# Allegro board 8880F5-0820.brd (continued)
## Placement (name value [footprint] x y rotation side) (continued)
NOREF#2148  -  []  192.47 182.06 90 top
NOREF#2149  -  []  201.21 290.01 90 top
NOREF#2150  -  []  237.83 197.63 0 top
NOREF#2151  -  []  373.93 297.12 0 top
NOREF#2152  -  []  343.31 164.72 0 top
NOREF#2153  -  []  328.01 286.96 0 top
NOREF#2154  -  []  210.86 214.75 90 top
NOREF#2155  -  []  419.9 272.82 90 top
NOREF#2156  -  []  247.78 140.14 0 top
NOREF#2157  -  []  385.61 208.66 90 top
NOREF#2158  -  []  256.45 224.72 0 top
NOREF#2159  -  []  383.09 273.11 0 top
NOREF#2160  -  []  384.17 180.15 90 top
NOREF#2161  -  []  331.94 204.65 90 top
NOREF#2162  -  []  118.7 195.7 0 top
NOREF#2163  -  []  75.98 273.87 90 top
NOREF#2164  -  []  288.74 290.13 90 top
NOREF#2165  -  []  101.82 287.84 90 top
NOREF#2166  -  []  390.53 154.88 0 top
NOREF#2167  -  []  419.9 272.92 90 top
NOREF#2168  -  []  305.83 264.31 0 top
NOREF#2169  -  []  175.7 230.17 90 top
NOREF#2170  -  []  412.62 289.12 0 top
NOREF#2171  -  []  408.28 129.99 0 top
NOREF#2172  -  []  253.4 265.56 0 top
NOREF#2173  -  []  465.45 290.38 90 top
NOREF#2174  -  []  262.04 224.72 0 top
NOREF#2175  -  []  118.7 222.88 0 top
NOREF#2176  -  []  369.63 273.11 0 top
NOREF#2177  -  []  352.55 182.64 0 top
NOREF#2178  -  []  265.64 280.1 0 top
NOREF#2179  -  []  371.73 297.12 0 top
NOREF#2180  -  []  165.8 226.57 90 top
NOREF#2181  -  []  331.38 163.52 90 top
NOREF#2182  -  []  327.15 286.96 90 top
NOREF#2183  -  []  386.53 164.91 90 top
NOREF#2184  -  []  127.59 211.59 90 top
NOREF#2185  -  []  168.13 145.38 90 top
NOREF#2186  -  []  310.41 183.09 90 top
NOREF#2187  -  []  381.74 265.11 0 top
NOREF#2188  -  []  184.47 173.11 90 top
NOREF#2189  -  []  121.9 231.22 0 top
NOREF#2190  -  []  167.7 255.15 90 top
NOREF#2191  -  []  317.57 269.63 90 top
NOREF#2192  -  []  250.17 165.04 90 top
NOREF#2193  -  []  309.21 193.37 0 top
NOREF#2194  -  []  472.86 217.98 90 top
NOREF#2195  -  []  256.77 223.82 90 top
NOREF#2196  -  []  247.57 204.65 90 top
NOREF#2197  -  []  322.62 139.64 0 top
NOREF#2198  -  []  409.74 163.69 90 top
NOREF#2199  -  []  379.01 272.66 90 top
NOREF#2200  -  []  343.95 164.74 90 top
NOREF#2201  -  []  398.65 225.11 0 top
NOREF#2202  -  []  251.94 265.86 90 top
NOREF#2203  -  []  271.34 181.37 0 top
NOREF#2204  -  []  209.33 187.82 90 top
NOREF#2205  -  []  409.49 180.15 0 top
NOREF#2206  -  []  208.98 257.6 90 top
NOREF#2207  -  []  390.94 241.16 90 top
NOREF#2208  -  []  386.46 131.89 0 top
NOREF#2209  -  []  247.57 264.65 90 top
NOREF#2210  -  []  424.47 163.09 90 top
NOREF#2211  -  []  165.8 144.78 0 top
NOREF#2212  -  []  406.19 171.64 0 top
NOREF#2213  -  []  273.09 288.41 90 top
NOREF#2214  -  []  412.79 209.16 90 top
NOREF#2215  -  []  310.43 186.34 90 top
NOREF#2216  -  []  249.28 225.04 90 top
NOREF#2217  -  []  383.09 224.85 0 top
NOREF#2218  -  []  451.68 239.34 0 top
NOREF#2219  -  []  400.85 281.11 0 top
NOREF#2220  -  []  328.96 224.74 0 top
NOREF#2221  -  []  218.16 248.49 0 top
NOREF#2222  -  []  271.34 241.37 0 top
NOREF#2223  -  []  222.11 240.71 0 top
NOREF#2224  -  []  306.85 211.67 0 top
NOREF#2225  -  []  165.8 199.39 0 top
NOREF#2226  -  []  343.98 288.86 0 top
NOREF#2227  -  []  184.47 186.57 0 top
NOREF#2228  -  []  184.47 214 0 top
NOREF#2229  -  []  210.6 255.9 90 top
NOREF#2230  -  []  352.25 184.86 90 top
NOREF#2231  -  []  230.73 253.69 0 top
NOREF#2232  -  []  184.47 200.54 0 top
NOREF#2233  -  []  312.79 288.86 90 top
NOREF#2234  -  []  271.04 189.18 0 top
NOREF#2235  -  []  388.43 163.64 0 top
NOREF#2236  -  []  167.7 214 90 top
NOREF#2237  -  []  238.3 224.74 90 top
NOREF#2238  -  []  182.57 254 90 top
NOREF#2239  -  []  165.8 212.85 0 top
NOREF#2240  -  []  297.41 213.24 90 top
NOREF#2241  -  []  122.19 247.3 90 top
NOREF#2242  -  []  218.16 237.06 0 top
NOREF#2243  -  []  304.61 144.34 0 top
NOREF#2244  -  []  352.55 242.64 0 top
NOREF#2245  -  []  331.94 264.65 90 top
NOREF#2246  -  []  199.33 212.85 0 top
NOREF#2247  -  []  383.83 209.11 0 top
NOREF#2248  -  []  112.16 238.84 0 top
NOREF#2249  -  []  223.56 233.86 90 top
NOREF#2250  -  []  221.56 190.49 0 top
NOREF#2251  -  []  209.59 174.36 90 top
NOREF#2252  -  []  460.93 191.31 90 top
NOREF#2253  -  []  287.91 280.1 0 top
NOREF#2254  -  []  230.73 243.41 0 top
NOREF#2255  -  []  501.87 276.41 90 top
NOREF#2256  -  []  405.17 131.89 0 top
NOREF#2257  -  []  328.96 164.74 0 top
NOREF#2258  -  []  385.32 161.49 90 top
NOREF#2259  -  []  296.96 240.71 0 top
NOREF#2260  -  []  375.73 196.98 90 top
NOREF#2261  -  []  332.51 205.56 90 top
NOREF#2262  -  []  168.13 186.02 90 top
NOREF#2263  -  []  175.7 182.06 90 top
NOREF#2264  -  []  104.18 191.95 0 top
NOREF#2265  -  []  337.09 163.52 90 top
NOREF#2266  -  []  259.33 205.56 90 top
NOREF#2267  -  []  201.23 241.43 90 top
NOREF#2268  -  []  381.2 242.38 90 top
NOREF#2269  -  []  229.51 186.66 0 top
NOREF#2270  -  []  310.73 253.69 0 top
NOREF#2271  -  []  468.68 129.54 0 top
NOREF#2272  -  []  199.84 148.65 90 top
NOREF#2273  -  []  471.11 230.2 0 top
NOREF#2274  -  []  165.8 254 90 top
NOREF#2275  -  []  250.49 164.74 90 top
NOREF#2276  -  []  230.73 249.2 0 top
NOREF#2277  -  []  330.49 223.52 90 top
NOREF#2278  -  []  168.13 227.17 90 top
NOREF#2279  -  []  201.23 204.09 90 top
NOREF#2280  -  []  306.27 216.63 90 top
NOREF#2281  -  []  232.25 211.67 90 top
NOREF#2282  -  []  240.94 151.63 90 top
NOREF#2283  -  []  237.57 209.63 90 top
NOREF#2284  -  []  327.25 265.56 90 top
NOREF#2285  -  []  271.31 288.86 0 top
NOREF#2286  -  []  322.23 233.13 0 top
NOREF#2287  -  []  392.24 199.18 90 top
NOREF#2288  -  []  182.82 175.58 90 top
NOREF#2289  -  []  383.07 163.44 90 top
NOREF#2290  -  []  348.28 296.86 0 top
NOREF#2291  -  []  272.24 183.59 90 top
NOREF#2292  -  []  260.99 135.19 90 top
NOREF#2293  -  []  249.85 224.74 0 top
NOREF#2294  -  []  108.27 178.64 0 top
NOREF#2295  -  []  184.47 187.92 90 top
NOREF#2296  -  []  199.59 145.03 0 top
NOREF#2297  -  []  224.65 271.67 0 top
NOREF#2298  -  []  250.17 223.82 90 top
NOREF#2299  -  []  251.38 224.74 90 top
NOREF#2300  -  []  167.7 132.72 90 top
NOREF#2301  -  []  332.83 204.65 90 top
NOREF#2302  -  []  369.38 224.6 0 top
NOREF#2303  -  []  339.65 265.86 90 top
NOREF#2304  -  []  166.06 175.58 90 top
NOREF#2305  -  []  413.1 144.98 0 top
NOREF#2306  -  []  383.09 241.11 0 top
NOREF#2307  -  []  419.73 131.89 90 top
NOREF#2308  -  []  301.56 242.89 0 top
NOREF#2309  -  []  306.83 209.63 90 top
NOREF#2310  -  []  390.69 289.12 0 top
NOREF#2311  -  []  230.43 248.88 0 top
NOREF#2312  -  []  404.4 241.16 90 top
NOREF#2313  -  []  390.69 273.11 0 top
NOREF#2314  -  []  339.33 265.56 90 top
NOREF#2315  -  []  271.34 189.5 0 top
NOREF#2316  -  []  254.29 205.55 0 top
NOREF#2317  -  []  339.33 265.55 0 top
NOREF#2318  -  []  396.55 241.11 0 top
NOREF#2319  -  []  257.9 246.35 90 top
NOREF#2320  -  []  334.29 265.56 0 top
NOREF#2321  -  []  397.8 163.09 90 top
NOREF#2322  -  []  331.86 252.43 90 top
NOREF#2323  -  []  209.23 216.45 90 top
NOREF#2324  -  []  251.54 252.73 90 top
NOREF#2325  -  []  209.23 250.38 90 top
NOREF#2326  -  []  320.42 131.64 0 top
NOREF#2327  -  []  287.27 286.96 90 top
NOREF#2328  -  []  306.71 144.34 0 top
NOREF#2329  -  []  258.2 246.67 0 top
NOREF#2330  -  []  194.09 201.29 90 top
NOREF#2331  -  []  230.43 247.61 90 top
NOREF#2332  -  []  385.93 161.74 0 top
NOREF#2333  -  []  88.64 247.45 90 top
NOREF#2334  -  []  394.05 239.21 0 top
NOREF#2335  -  []  96.58 195.15 0 top
NOREF#2336  -  []  228.36 202.16 45 top
NOREF#2337  -  []  462.06 291.28 90 top
NOREF#2338  -  []  336.77 223.82 90 top
NOREF#2339  -  []  118.45 226.62 90 top
NOREF#2340  -  []  468.01 171.53 0 top
NOREF#2341  -  []  254.29 265.56 90 top
NOREF#2342  -  []  379.48 239.21 90 top
NOREF#2343  -  []  312.46 144.39 90 top
NOREF#2344  -  []  351.04 189.18 0 top
NOREF#2345  -  []  235.85 288.61 90 top
NOREF#2346  -  []  184.47 244.98 90 top
NOREF#2347  -  []  247.57 205.86 90 top
NOREF#2348  -  []  228.36 262.16 45 top
NOREF#2349  -  []  400.54 171.64 0 top
NOREF#2350  -  []  351.04 189.82 0 top
NOREF#2351  -  []  167.7 173.11 0 top
NOREF#2352  -  []  301.56 239.06 0 top
NOREF#2353  -  []  217.83 234.63 90 top
NOREF#2354  -  []  119.95 187.53 0 top
NOREF#2355  -  []  262.36 165.04 90 top
NOREF#2356  -  []  272.55 249.5 0 top
NOREF#2357  -  []  177.33 173.86 90 top
NOREF#2358  -  []  331.54 192.73 90 top
NOREF#2359  -  []  184.47 231.27 90 top
NOREF#2360  -  []  209.23 243.88 90 top
NOREF#2361  -  []  309.21 248.88 0 top
NOREF#2362  -  []  415.61 183.52 90 top
NOREF#2363  -  []  376.23 209.11 0 top
NOREF#2364  -  []  201.49 146.18 0 top
NOREF#2365  -  []  106.76 222.88 0 top
NOREF#2366  -  []  248.96 224.74 0 top
NOREF#2367  -  []  339.33 264.35 90 top
NOREF#2368  -  []  351.34 189.5 0 top
NOREF#2369  -  []  251.62 264.35 90 top
NOREF#2370  -  []  395.2 249.11 0 top
NOREF#2371  -  []  107.76 238.84 0 top
NOREF#2372  -  []  298.16 177.06 0 top
NOREF#2373  -  []  184.47 241.43 0 top
NOREF#2374  -  []  200.98 260.9 90 top
NOREF#2375  -  []  251.62 205.55 0 top
NOREF#2376  -  []  209.49 150.83 90 top
NOREF#2377  -  []  318.45 197.01 0 top
NOREF#2378  -  []  375.73 194.78 90 top
NOREF#2379  -  []  230.43 193.37 90 top
NOREF#2380  -  []  249.28 223.82 90 top
NOREF#2381  -  []  182.57 144.78 0 top
NOREF#2382  -  []  254.61 205.86 90 top
NOREF#2383  -  []  167.7 145.93 90 top
NOREF#2384  -  []  317.05 288.86 0 top
NOREF#2385  -  []  110.21 195.15 0 top
NOREF#2386  -  []  351.04 241.69 0 top
NOREF#2387  -  []  380.59 271.21 0 top
NOREF#2388  -  []  294.94 296.86 0 top
NOREF#2389  -  []  184.89 172.56 90 top
NOREF#2390  -  []  286.55 288.41 90 top
NOREF#2391  -  []  329.28 165.04 90 top
NOREF#2392  -  []  478.57 257.36 90 top
NOREF#2393  -  []  317.98 223.82 90 top
NOREF#2394  -  []  272.55 183.91 0 top
NOREF#2395  -  []  261.63 233.83 90 top
NOREF#2396  -  []  209.23 222.95 90 top
NOREF#2397  -  []  108.01 222.33 0 top
NOREF#2398  -  []  250.74 164.72 0 top
NOREF#2399  -  []  449.99 217.9 0 top
NOREF#2400  -  []  390.69 224.85 0 top
NOREF#2401  -  []  302.11 192.14 0 top
NOREF#2402  -  []  393.19 222.95 90 top
NOREF#2403  -  []  403.41 209.61 0 top
NOREF#2404  -  []  272.25 244.86 90 top
NOREF#2405  -  []  425.2 161.74 90 top
NOREF#2406  -  []  216.96 192.14 0 top
NOREF#2407  -  []  272.25 183.59 90 top
NOREF#2408  -  []  285.02 288.91 90 top
NOREF#2409  -  []  252.83 264.65 90 top
NOREF#2410  -  []  84.04 290.38 90 top
NOREF#2411  -  []  216.96 240.71 0 top
NOREF#2412  -  []  127.55 191.95 90 top
NOREF#2413  -  []  327.25 204.35 90 top
NOREF#2414  -  []  201.21 292.55 90 top
NOREF#2415  -  []  414.82 249.11 0 top
NOREF#2416  -  []  201.49 165.4 90 top
NOREF#2417  -  []  230.73 193.69 0 top
NOREF#2418  -  []  168.13 213.45 90 top
NOREF#2419  -  []  411.26 163.19 90 top
NOREF#2420  -  []  217.41 213.24 0 top
NOREF#2421  -  []  293.66 272.15 90 top
NOREF#2422  -  []  184.47 260.9 90 top
NOREF#2423  -  []  420.15 131.44 90 top
NOREF#2424  -  []  251.62 265.56 0 top
NOREF#2425  -  []  103.93 235.64 0 top
NOREF#2426  -  []  250.74 224.72 0 top
NOREF#2427  -  []  172.08 291.65 90 top
NOREF#2428  -  []  107.02 179.19 0 top
NOREF#2429  -  []  300.36 188.49 0 top
NOREF#2430  -  []  409.17 281.37 0 top
NOREF#2431  -  []  230.73 183.41 0 top
NOREF#2432  -  []  167.7 163.2 90 top
NOREF#2433  -  []  401.89 180.15 0 top
NOREF#2434  -  []  367.73 274.38 90 top
NOREF#2435  -  []  332.51 265.56 0 top
NOREF#2436  -  []  309.51 243.41 0 top
NOREF#2437  -  []  483.04 239.09 0 top
NOREF#2438  -  []  118.45 234.24 90 top
NOREF#2439  -  []  211.11 146.93 90 top
NOREF#2440  -  []  298.13 274.06 90 top
NOREF#2441  -  []  368.03 249.11 0 top
NOREF#2442  -  []  98.53 238.84 0 top
NOREF#2443  -  []  242.23 233.13 90 top
NOREF#2444  -  []  182.57 144.78 90 top
NOREF#2445  -  []  221.87 295.91 0 top
NOREF#2446  -  []  331.94 205.86 90 top
NOREF#2447  -  []  175.7 202.99 90 top
NOREF#2448  -  []  221.56 242.89 0 top
NOREF#2449  -  []  369.38 241.11 0 top
NOREF#2450  -  []  424.55 146.88 90 top
NOREF#2451  -  []  400.85 233.11 0 top
NOREF#2452  -  []  253.33 241.33 90 top
NOREF#2453  -  []  209.49 168.6 90 top
NOREF#2454  -  []  222.11 192.14 0 top
NOREF#2455  -  []  262.68 164.74 90 top
NOREF#2456  -  []  449.99 174.46 0 top
NOREF#2457  -  []  185.2 290.01 90 top
NOREF#2458  -  []  165.8 240.28 90 top
NOREF#2459  -  []  399.99 164.91 90 top
NOREF#2460  -  []  400.85 297.12 0 top
NOREF#2461  -  []  251.62 204.35 90 top
NOREF#2462  -  []  459.28 236.14 0 top
NOREF#2463  -  []  392.24 196.98 90 top
NOREF#2464  -  []  165.8 171.96 90 top
NOREF#2465  -  []  252.83 204.65 90 top
NOREF#2466  -  []  199.59 171.96 90 top
NOREF#2467  -  []  201.23 247.18 90 top
NOREF#2468  -  []  127.84 167.9 90 top
NOREF#2469  -  []  396.55 241.11 0 top
NOREF#2470  -  []  201.49 178.86 90 top
NOREF#2471  -  []  317.57 209.63 90 top
NOREF#2472  -  []  330.17 223.82 90 top
NOREF#2473  -  []  192.47 150.58 90 top
NOREF#2474  -  []  192.47 257.6 90 top
NOREF#2475  -  []  461.86 187.32 0 top
NOREF#2476  -  []  330.49 164.74 90 top
NOREF#2477  -  []  175.8 147.18 90 top
NOREF#2478  -  []  331.05 264.65 90 top
NOREF#2479  -  []  251.06 225.04 90 top
NOREF#2480  -  []  343.95 224.74 90 top
NOREF#2481  -  []  308.91 152.34 0 top
NOREF#2482  -  []  342.04 224.74 0 top
NOREF#2483  -  []  107.02 171.57 0 top
NOREF#2484  -  []  262.04 224.74 0 top
NOREF#2485  -  []  263.63 225.04 90 top
NOREF#2486  -  []  201.23 233.47 90 top
NOREF#2487  -  []  199.33 240.28 90 top
NOREF#2488  -  []  215.96 237.06 0 top
NOREF#2489  -  []  313.22 288.31 90 top
NOREF#2490  -  []  328.42 129.74 90 top
NOREF#2491  -  []  352.55 183.91 0 top
NOREF#2492  -  []  377.32 180.15 0 top
NOREF#2493  -  []  412.62 241.11 0 top
NOREF#2494  -  []  459.24 175.86 90 top
NOREF#2495  -  []  230.43 253.37 0 top
NOREF#2496  -  []  209.23 202.99 90 top
NOREF#2497  -  []  247.25 265.56 90 top
NOREF#2498  -  []  266.74 272.1 0 top
NOREF#2499  -  []  392.66 192.88 90 top
NOREF#2500  -  []  306.83 269.63 90 top
NOREF#2501  -  []  201.66 240.88 90 top
NOREF#2502  -  []  106.76 215.26 0 top
NOREF#2503  -  []  256.45 164.72 0 top
NOREF#2504  -  []  221.56 250.49 0 top
NOREF#2505  -  []  329.6 224.74 90 top
NOREF#2506  -  []  263.63 165.04 90 top
NOREF#2507  -  []  310.43 193.37 90 top
NOREF#2508  -  []  201.66 213.45 90 top
NOREF#2509  -  []  460.89 217.9 90 top
NOREF#2510  -  []  226.27 216.63 90 top
NOREF#2511  -  []  373.68 232.6 0 top
NOREF#2512  -  []  408.02 287.22 0 top
NOREF#2513  -  []  175.7 195.52 90 top
NOREF#2514  -  []  167.7 233.47 90 top
NOREF#2515  -  []  250.74 164.74 0 top
NOREF#2516  -  []  127.55 219.13 90 top
NOREF#2517  -  []  401.89 163.64 0 top
NOREF#2518  -  []  250.73 204.35 90 top
NOREF#2519  -  []  450.03 182.17 0 top
NOREF#2520  -  []  201.49 146.18 90 top
NOREF#2521  -  []  377.48 289.17 90 top
NOREF#2522  -  []  270.29 135.24 90 top
NOREF#2523  -  []  257.9 246.99 0 top
NOREF#2524  -  []  380.59 222.95 0 top
NOREF#2525  -  []  332.61 288.86 0 top
NOREF#2526  -  []  210.86 201.29 90 top
NOREF#2527  -  []  392.47 288.67 90 top
NOREF#2528  -  []  166.06 230.19 90 top
NOREF#2529  -  []  389.7 209.36 0 top
NOREF#2530  -  []  101.82 273.87 90 top
NOREF#2531  -  []  485.36 257.36 90 top
NOREF#2532  -  []  383.09 273.11 0 top
NOREF#2533  -  []  295.96 237.06 0 top
NOREF#2534  -  []  208.98 264.1 90 top
NOREF#2535  -  []  351.34 241.37 0 top
NOREF#2536  -  []  315.82 129.74 0 top
NOREF#2537  -  []  175.7 168.6 90 top
NOREF#2538  -  []  354.37 130.67 90 top
NOREF#2539  -  []  247.57 264.65 90 top
NOREF#2540  -  []  192.57 242.68 90 top
NOREF#2541  -  []  456.08 239.34 0 top
NOREF#2542  -  []  184.47 206.29 90 top
NOREF#2543  -  []  155.57 272.6 90 top
NOREF#2544  -  []  405.93 240.66 90 top
NOREF#2545  -  []  230.41 246.34 90 top
NOREF#2546  -  []  371.73 273.11 0 top
NOREF#2547  -  []  314.33 228.13 90 top
NOREF#2548  -  []  230.43 188.88 90 top
NOREF#2549  -  []  217.83 174.63 90 top
NOREF#2550  -  []  264.29 272.1 90 top
NOREF#2551  -  []  329.28 223.82 90 top
NOREF#2552  -  []  339.89 288.31 90 top
NOREF#2553  -  []  272.25 181.69 0 top
NOREF#2554  -  []  412.62 281.37 0 top
NOREF#2555  -  []  559.43 297.18 90 top
NOREF#2556  -  []  352.24 184.86 90 top
NOREF#2557  -  []  175.7 175.56 90 top
NOREF#2558  -  []  119.95 195.15 0 top
NOREF#2559  -  []  459.28 227 90 top
NOREF#2560  -  []  272.25 242.96 0 top
NOREF#2561  -  []  256.77 165.04 90 top
NOREF#2562  -  []  318.32 131.64 0 top
NOREF#2563  -  []  467.51 230.2 0 top
NOREF#2564  -  []  119.7 231.22 0 top
NOREF#2565  -  []  377.23 273.11 0 top
NOREF#2566  -  []  344.37 128.27 0 top
NOREF#2567  -  []  478.57 259.9 90 top
NOREF#2568  -  []  247.57 265.86 90 top
NOREF#2569  -  []  461.96 174.55 0 top
NOREF#2570  -  []  201.49 173.11 0 top
NOREF#2571  -  []  271.04 185.5 0 top
NOREF#2572  -  []  463.61 171.53 0 top
R1  NC/1M-1-S4  [R0402]  221.23 227.84 180 bottom
R2  NC/1M-1-S4  [R0402]  218.95 227.84 0 bottom
R3  NC/100K-1-S4  [R0402]  184.15 131.06 180 bottom
R4  NC/100K-1-S4  [R0402]  181.61 131.06 180 bottom
R5  0-5-S4  [R0402]  222.38 272.16 270 bottom
R6  1M-1-S4  [R0402]  222.38 274.32 270 bottom
R7  49.9-1-S4  [R0402]  178.5 217.52 90 bottom
R8  49.9-1-S4  [R0402]  178.5 215.38 90 bottom
R9  49.9-1-S4  [R0402]  164.91 217.52 90 bottom
R10  49.9-1-S4  [R0402]  164.91 215.38 90 bottom
R11  49.9-1-S4  [R0402]  212.03 231.24 90 bottom
R12  49.9-1-S4  [R0402]  212.03 229.1 90 bottom
R13  49.9-1-S4  [R0402]  198.44 231.24 90 bottom
R14  49.9-1-S4  [R0402]  198.44 229.1 90 bottom
R15  49.9-1-S4  [R0402]  296.06 299.66 180 bottom
R16  49.9-1-S4  [R0402]  298.21 299.66 180 bottom
R17  49.9-1-S4  [R0402]  296.06 286.07 180 bottom
R18  49.9-1-S4  [R0402]  298.21 286.07 180 bottom
R19  49.9-1-S4  [R0402]  309.27 299.66 180 bottom
R20  49.9-1-S4  [R0402]  311.42 299.66 180 bottom
R21  49.9-1-S4  [R0402]  309.27 286.07 180 bottom
R22  49.9-1-S4  [R0402]  311.42 286.07 180 bottom
R23  49.9-1-S4  [R0402]  349.4 299.66 180 bottom
R24  49.9-1-S4  [R0402]  351.55 299.66 180 bottom
R25  49.9-1-S4  [R0402]  349.4 286.07 180 bottom
R26  49.9-1-S4  [R0402]  351.55 286.07 180 bottom
R27  49.9-1-S4  [R0402]  335.94 299.66 180 bottom
R28  49.9-1-S4  [R0402]  338.09 299.66 180 bottom
R29  49.9-1-S4  [R0402]  335.94 286.07 180 bottom
R30  49.9-1-S4  [R0402]  338.09 286.07 180 bottom
R31  49.9-1-S4  [R0402]  322.48 299.66 180 bottom
R32  49.9-1-S4  [R0402]  324.62 299.66 180 bottom
R33  49.9-1-S4  [R0402]  322.48 286.07 180 bottom
R34  49.9-1-S4  [R0402]  324.62 286.07 180 bottom
R37  49.9-1-S4  [R0402]  269.14 286.07 180 bottom
R38  49.9-1-S4  [R0402]  271.28 286.07 180 bottom
R39  49.9-1-S4  [R0402]  287.88 269.3 0 bottom
R40  49.9-1-S4  [R0402]  285.74 269.3 0 bottom
R41  49.9-1-S4  [R0402]  287.88 282.89 0 bottom
R42  49.9-1-S4  [R0402]  285.74 282.89 0 bottom
R43  49.9-1-S4  [R0402]  164.91 258.67 90 bottom
R44  49.9-1-S4  [R0402]  164.91 256.53 90 bottom
R45  49.9-1-S4  [R0402]  198.44 244.96 90 bottom
R46  49.9-1-S4  [R0402]  198.44 242.81 90 bottom
R47  49.9-1-S4  [R0402]  195.26 231.24 90 bottom
R48  49.9-1-S4  [R0402]  195.26 229.1 90 bottom
R49  49.9-1-S4  [R0402]  181.67 231.24 90 bottom
R50  49.9-1-S4  [R0402]  181.67 229.1 90 bottom
R51  49.9-1-S4  [R0402]  178.5 231.24 90 bottom
R52  49.9-1-S4  [R0402]  178.5 229.1 90 bottom
R53  49.9-1-S4  [R0402]  164.91 231.24 90 bottom
R54  49.9-1-S4  [R0402]  164.91 229.1 90 bottom
R55  49.9-1-S4  [R0402]  211.77 258.67 90 bottom
R56  49.9-1-S4  [R0402]  211.77 256.53 90 bottom
R57  49.9-1-S4  [R0402]  198.18 258.67 90 bottom
R58  49.9-1-S4  [R0402]  198.18 256.53 90 bottom
R59  49.9-1-S4  [R0402]  195.26 244.96 90 bottom
R60  49.9-1-S4  [R0402]  195.26 242.81 90 bottom
R61  49.9-1-S4  [R0402]  181.67 244.96 90 bottom
R62  49.9-1-S4  [R0402]  181.67 242.81 90 bottom
R63  49.9-1-S4  [R0402]  195.26 258.67 90 bottom
R64  49.9-1-S4  [R0402]  195.26 256.53 90 bottom
R65  49.9-1-S4  [R0402]  164.91 244.96 90 bottom
R66  49.9-1-S4  [R0402]  164.91 242.81 90 bottom
R67  49.9-1-S4  [R0402]  239.37 285.81 0 bottom
R68  49.9-1-S4  [R0402]  237.22 285.81 0 bottom
R69  49.9-1-S4  [R0402]  239.37 299.4 0 bottom
R70  49.9-1-S4  [R0402]  237.22 299.4 0 bottom
R71  49.9-1-S4  [R0402]  255.93 299.66 180 bottom
R72  49.9-1-S4  [R0402]  258.08 299.66 180 bottom
R73  49.9-1-S4  [R0402]  255.93 286.07 180 bottom
R74  49.9-1-S4  [R0402]  258.08 286.07 180 bottom
R75  49.9-1-S4  [R0402]  282.6 299.66 180 bottom
R76  49.9-1-S4  [R0402]  284.75 299.66 180 bottom
R77  49.9-1-S4  [R0402]  282.6 286.07 180 bottom
R78  49.9-1-S4  [R0402]  284.75 286.07 180 bottom
R79  49.9-1-S4  [R0402]  178.5 258.67 90 bottom
R80  49.9-1-S4  [R0402]  178.5 256.53 90 bottom
R82  4.7K-1-S4-WA  [R0402]  122.62 241.1 180 bottom
R83  4.7K-1-S4-WA  [R0402]  96.77 233.43 180 bottom
R84  4.7K-1-S4-WA  [R0402]  96.77 241.05 180 bottom
R85  100K-1-S4  [R0402]  113.79 230.12 180 bottom
R86  4.7K-1-S4-WA  [R0402]  93.33 207.46 180 bottom
R87  4.7K-1-S4-WA  [R0402]  104.14 203.31 180 bottom
R88  4.7K-1-S4-WA  [R0402]  101.6 203.31 180 bottom
R89  4.7K-1-S4-WA  [R0402]  89.03 207.41 0 bottom
R90  4.7K-1-S4-WA  [R0402]  101.6 215.5 180 bottom
R91  4.7K-1-S4-WA  [R0402]  99.06 215.5 180 bottom
R92  4.7K-1-S4-WA  [R0402]  96.52 215.5 180 bottom
R93  4.7K-1-S4-WA  [R0402]  93.33 221.18 180 bottom
R94  4.7K-1-S4-WA  [R0402]  104.25 216.86 0 bottom
R95  4.7K-1-S4-WA  [R0402]  101.7 216.91 180 bottom
R96  4.7K-1-S4-WA  [R0402]  89.27 221.18 0 bottom
R97  4.7K-1-S4-WA  [R0402]  101.7 229.1 180 bottom
R98  4.7K-1-S4-WA  [R0402]  99.16 229.1 180 bottom
R99  4.7K-1-S4-WA  [R0402]  96.62 229.1 180 bottom
R100  49.9-1-S4  [R0402]  181.67 258.67 90 bottom
R101  49.9-1-S4  [R0402]  181.67 256.53 90 bottom
R102  49.9-1-S4  [R0402]  212.03 244.96 90 bottom
R103  49.9-1-S4  [R0402]  212.03 242.81 90 bottom
R104  49.9-1-S4  [R0402]  178.5 244.96 90 bottom
R105  49.9-1-S4  [R0402]  178.5 242.81 90 bottom
R117  1K-1-S4  [R0402]  127.2 241.1 180 bottom
R118  NC/0-5-S4  [R0402]  230.41 245.39 180 bottom
R119  4.7K-1-S4-WA  [R0402]  127.25 233.43 0 bottom
R120  4.7K-1-S4-WA  [R0402]  127.25 225.81 0 bottom
R125  0-5-S4  [R0402]  123.19 224.54 180 bottom
R126  0-5-S4  [R0402]  127.25 224.54 180 bottom
R127  0-5-S4  [R0402]  122.94 216.92 180 bottom
R128  0-5-S4  [R0402]  127.51 216.92 180 bottom
R129  0-5-S4  [R0402]  221.23 229.11 180 bottom
R130  0-5-S4  [R0402]  218.95 229.11 0 bottom
R131  50-0.1-S4-HF-VI  [R0402]  223.77 243.33 90 bottom
R132  50-0.1-S4-HF-VI  [R0402]  216.15 243.33 90 bottom
R133  0-5-S4  [R0402]  222.38 276.48 90 bottom
RB1  10K-1-S6  [R0603]  212.47 13.59 0 bottom
RB2  10K-1-S6  [R0603]  212.47 12.06 0 bottom
S1_I2C  HDR-4X1-MR-A  [JP_4P_100_R90_V1]  62.99 209.04 270 top
S1_RST_N  HDR-2X1-M  [JP_2P_100]  115.82 232.41 270 bottom
S2_I2C  HDR-4X1-MR-A  [JP_4P_100_R90_V1]  497.33 203.45 270 top
S2_RST_N  HDR-2X1-M  [JP_2P_100]  463.04 233.43 90 bottom
S3_I2C  HDR-4X1-MR-A  [JP_4P_100_R90_V1]  75.69 209.04 270 top
S3_RST_N  HDR-2X1-M  [JP_2P_100]  116.08 188.72 270 bottom
S4_I2C  HDR-4X1-MR-A  [JP_4P_100_R90_V1]  511.3 203.45 270 top
S4_RST_N  HDR-2X1-M  [JP_2P_100]  463.04 189.99 90 bottom
SB1  SHORT  [DEFAULT_SHORT_SMALL]  402.59 11.04 90 top
SB2  SHORT  [DEFAULT_SHORT_SMALL]  328.93 417.83 270 top
SB3  SHORT  [DEFAULT_SHORT_SMALL]  255.27 11.71 90 top
SB8  SHORT  [DEFAULT_SHORT_SMALL]  179.07 418.32 270 top
SCREW1  V93KMFHOLE  [PG_VG93K_F_FULLOUTLINE]  290.83 214.63 0 top
SH1  SHORT  [DEFAULT_SHORT_SMALL]  185.19 290.72 0 top
SH2  SHORT  [DEFAULT_SHORT_SMALL]  187.14 290.72 0 top
SH3  SHORT  [DEFAULT_SHORT_SMALL]  175.35 290.72 0 top
SH4  SHORT  [DEFAULT_SHORT_SMALL]  173.4 290.85 180 top
SH5  SHORT  [DEFAULT_SHORT_SMALL]  118.2 289.45 0 top
SH6  SHORT  [DEFAULT_SHORT_SMALL]  116.25 289.58 180 top
SH7  SHORT  [DEFAULT_SHORT_SMALL]  168.68 290.72 0 top
SH8  SHORT  [DEFAULT_SHORT_SMALL]  156.89 290.85 180 top
SH9  SHORT  [DEFAULT_SHORT_SMALL]  170.63 290.72 0 top
SH10  SHORT  [DEFAULT_SHORT_SMALL]  158.84 290.72 0 top
SH11  SHORT  [DEFAULT_SHORT_SMALL]  173.4 274.34 180 top
SH12  SHORT  [DEFAULT_SHORT_SMALL]  185.19 274.21 0 top
SH13  SHORT  [DEFAULT_SHORT_SMALL]  203.14 290.72 0 top
SH14  SHORT  [DEFAULT_SHORT_SMALL]  201.19 290.72 0 top
SH15  SHORT  [DEFAULT_SHORT_SMALL]  189.4 290.85 180 top
SH16  SHORT  [DEFAULT_SHORT_SMALL]  191.35 290.72 0 top
SH17  SHORT  [DEFAULT_SHORT_SMALL]  156.89 274.34 180 top
SH18  SHORT  [DEFAULT_SHORT_SMALL]  168.68 274.21 0 top
SH19  SHORT  [DEFAULT_SHORT_SMALL]  99.42 246.45 0 top
SH20  SHORT  [DEFAULT_SHORT_SMALL]  101.62 246.45 0 top
SH21  SHORT  [DEFAULT_SHORT_SMALL]  94.56 246.5 0 top
SH22  SHORT  [DEFAULT_SHORT_SMALL]  96.76 246.5 0 top
SH23  SHORT  [DEFAULT_SHORT_SMALL]  201.19 274.21 0 top
SH24  SHORT  [DEFAULT_SHORT_SMALL]  203.37 274.08 180 top
SH25  SHORT  [DEFAULT_SHORT_SMALL]  175.35 274.21 0 top
SH26  SHORT  [DEFAULT_SHORT_SMALL]  187.14 274.21 0 top
SH27  SHORT  [DEFAULT_SHORT_SMALL]  158.84 274.21 0 top
SH28  SHORT  [DEFAULT_SHORT_SMALL]  170.63 274.21 0 top
SITE1  CU/HX8880-F05-LQFP176-20X20  [SK_LQFP176P_0P4MM_JG_HX8880]  250.83 244.63 90 top
SITE2  CU/HX8880-F05-LQFP176-20X20  [SK_LQFP176P_0P4MM_JG_HX8880]  330.83 244.63 90 top
SITE3  CU/HX8880-F05-LQFP176-20X20  [SK_LQFP176P_0P4MM_JG_HX8880]  250.83 184.63 90 top
SITE4  CU/HX8880-F05-LQFP176-20X20  [SK_LQFP176P_0P4MM_JG_HX8880]  330.83 184.63 90 top
SKB  Socket_Base_M5_140x140  [SOCKET_BASE_140X140_565100]  290.83 214.63 0 top
TP_AUXVCC  TP01  [TP_040_T]  101.29 247.61 180 top
TP_AVDD11_RX  TP01  [TP_040_T]  158.96 292.1 180 top
TP_AVDD11_XTAL  TP01  [TP_040_T]  201.21 275.59 0 top
TP_AVDD18_RX  TP01  [TP_040_T]  168.7 292.1 0 top
TP_PLL_M_VDD33  TP01  [TP_040_T]  201.21 292.1 0 top
TP_PLL_TX_VDD33  TP01  [TP_040_T]  191.48 292.1 180 top
TP_VCC3V3  TP01  [TP_040_T]  96.42 247.66 180 top
TP_VDD_IO_33  TP01  [TP_040_T]  175.47 292.1 180 top
TP_VDD_TXREG_33_B  TP01  [TP_040_T]  168.7 275.59 0 top
TP_VDD_TXREG_33_T  TP01  [TP_040_T]  158.96 275.59 180 top
TP_VDDA_33_LV  TP01  [TP_040_T]  185.21 292.1 0 top
TP_VDDC_11  TP01  [TP_040_T]  118.32 290.83 180 top
TP_VDDTXPST_11_B  TP01  [TP_040_T]  185.21 275.59 0 top
TP_VDDTXPST_11_T  TP01  [TP_040_T]  175.47 275.59 180 top
TP_XTAL_IN  TP01  [TP_040_T]  226.85 271.67 0 top
TP_XTAL_OUT  TP01  [TP_040_T]  226.85 276.97 0 top
TPL1  TPL01  [TPL_040_014_TB]  73.41 239.01 0 top
TPL2  TPL01  [TPL_040_014_TB]  78.49 244.09 0 top
TPL3  TPL01  [TPL_040_014_TB]  68.33 228.85 0 top
TPL4  TPL01  [TPL_040_014_TB]  68.33 239.01 0 top
TPL5  TPL01  [TPL_040_014_TB]  73.41 244.09 0 top
TPL6  TPL01  [TPL_040_014_TB]  68.33 233.93 0 top
TPL7  TPL01  [TPL_040_014_TB]  78.49 233.93 0 top
TPL8  TPL01  [TPL_040_014_TB]  73.41 233.93 0 top
TPL9  TPL01  [TPL_040_014_TB]  68.33 244.09 0 top
TPL10  TPL01  [TPL_040_014_TB]  78.49 239.01 0 top
TPL11  TPL01  [TPL_040_014_TB]  73.41 218.69 0 top
TPL12  TPL01  [TPL_040_014_TB]  78.49 218.69 0 top
TPL13  TPL01  [TPL_040_014_TB]  83.57 223.77 0 top
TPL14  TPL01  [TPL_040_014_TB]  83.57 218.69 0 top
TPL15  TPL01  [TPL_040_014_TB]  73.41 228.85 0 top
TPL16  TPL01  [TPL_040_014_TB]  68.33 223.77 0 top
TPL17  TPL01  [TPL_040_014_TB]  68.33 218.69 0 top
TPL18  TPL01  [TPL_040_014_TB]  78.49 223.77 0 top
TPL19  TPL01  [TPL_040_014_TB]  73.41 223.77 0 top
TPL20  TPL01  [TPL_040_014_TB]  78.49 228.85 0 top
TPL21  TPL01  [TPL_040_014_TB]  452.63 249.17 0 top
TPL22  TPL01  [TPL_040_014_TB]  452.63 259.33 0 top
TPL23  TPL01  [TPL_040_014_TB]  452.63 264.41 0 top
TPL24  TPL01  [TPL_040_014_TB]  452.63 254.25 0 top
TPL25  TPL01  [TPL_040_014_TB]  452.63 244.09 0 top
TPL26  TPL01  [TPL_040_014_TB]  457.71 244.09 0 top
TPL27  TPL01  [TPL_040_014_TB]  452.63 269.49 0 top
TPL28  TPL01  [TPL_040_014_TB]  457.71 249.17 0 top
TPL29  TPL01  [TPL_040_014_TB]  457.71 269.49 0 top
TPL30  TPL01  [TPL_040_014_TB]  457.71 264.41 0 top
TPL31  TPL01  [TPL_040_014_TB]  457.71 259.33 0 top
TPL32  TPL01  [TPL_040_014_TB]  457.71 254.25 0 top
TPL33  TPL01  [TPL_040_014_TB]  462.79 244.09 0 top
TPL34  TPL01  [TPL_040_014_TB]  467.87 249.17 0 top
TPL35  TPL01  [TPL_040_014_TB]  467.87 244.09 0 top
TPL36  TPL01  [TPL_040_014_TB]  462.79 249.17 0 top
TPL37  TPL01  [TPL_040_014_TB]  462.79 269.49 0 top
TPL38  TPL01  [TPL_040_014_TB]  462.79 259.33 0 top
TPL39  TPL01  [TPL_040_014_TB]  462.79 254.25 0 top
TPL40  TPL01  [TPL_040_014_TB]  462.79 264.41 0 top
U1  SOLDER-DIP8-SOCKET  [DIP8_300X100_RLPIN]  104.66 205.54 90 bottom
U2  SOLDER-DIP8-SOCKET  [DIP8_300X100_RLPIN]  104.76 219.15 90 bottom
UB1  AT24C04C-SSHM-SO8  [SO8_215X127MM]  218.44 13.97 180 bottom
UF1  MX25L4006EM2I-12G-SOP8  [SOCKET_CODE]  104.66 205.54 270 top
UF2  MX25L4006EM2I-12G-SOP8  [SOCKET_CODE]  104.75 219.2 270 top
UNK2C3  0.1U-16-X-S4-MU  [C0402]  289.81 132.08 180 bottom
UNK2C4  0.1U-16-X-S4-MU  [C0402]  287.27 132.08 180 bottom
UNK2C5  22P-50-N-S4-AVX  [C0402]  301.21 277.48 90 bottom
UNK2C6  22P-50-N-S4-AVX  [C0402]  301.21 271.16 270 bottom
UNK2C7  0.1U-16-X-S4-MU  [C0402]  468.12 235.71 180 bottom
UNK2C8  0.1U-16-X-S4-MU  [C0402]  475.39 204.98 0 bottom
UNK2C9  0.1U-16-X-S4-MU  [C0402]  475.49 218.59 0 bottom
UNK2CA1  NC/10U-10-X6S-S6-MU  [C0603]  462.91 293.37 0 bottom
UNK2CA2  NC/47U-10-X5R-S8-TDK  [C0805]  463.02 295.27 0 bottom
UNK2CA3  NC/10U-10-X6S-S6-MU  [C0603]  451.49 293.37 180 bottom
UNK2CA4  NC/47U-10-X5R-S8-TDK  [C0805]  451.38 295.27 180 bottom
UNK2CA5  NC/10U-10-X6S-S6-MU  [C0603]  484.5 293.37 180 bottom
UNK2CA6  NC/47U-10-X5R-S8-TDK  [C0805]  484.4 295.27 180 bottom
UNK2CA7  NC/10U-10-X6S-S6-MU  [C0603]  462.91 276.86 0 bottom
UNK2CA8  NC/47U-10-X5R-S8-TDK  [C0805]  463.02 278.76 0 bottom
UNK2CA9  NC/10U-10-X6S-S6-MU  [C0603]  451.49 276.86 180 bottom
UNK2CA10  NC/47U-10-X5R-S8-TDK  [C0805]  451.38 278.76 180 bottom
UNK2CA11  NC/10U-10-X6S-S6-MU  [C0603]  495.93 276.86 0 bottom
UNK2CA12  NC/47U-10-X5R-S8-TDK  [C0805]  496.04 278.76 0 bottom
UNK2CA13  NC/47U-10-X5R-S8-TDK  [C0805]  479.53 295.27 0 bottom
UNK2CA14  NC/10U-10-X6S-S6-MU  [C0603]  479.42 293.37 0 bottom
UNK2CA15  NC/47U-10-X5R-S8-TDK  [C0805]  467.89 295.27 180 bottom
UNK2CA16  NC/10U-10-X6S-S6-MU  [C0603]  468 293.37 180 bottom
UNK2CA17  NC/47U-10-X5R-S8-TDK  [C0805]  479.53 278.76 0 bottom
UNK2CA18  NC/10U-10-X6S-S6-MU  [C0603]  479.42 276.86 0 bottom
UNK2CA19  NC/47U-10-X5R-S8-TDK  [C0805]  91.09 249.81 180 bottom
UNK2CA20  NC/10U-10-X6S-S6-MU  [C0603]  91.19 247.9 180 bottom
UNK2CA21  10U-10-X6S-S6-MU  [C0603]  462.91 290.83 0 bottom
UNK2CA22  10U-10-X6S-S6-MU  [C0603]  451.49 290.83 180 bottom
UNK2CA23  10U-10-X6S-S6-MU  [C0603]  484.5 290.83 180 bottom
UNK2CA24  10U-10-X6S-S6-MU  [C0603]  462.91 274.32 0 bottom
UNK2CA25  10U-10-X6S-S6-MU  [C0603]  451.49 274.32 180 bottom
UNK2CA26  10U-10-X6S-S6-MU  [C0603]  495.93 274.32 0 bottom
UNK2CA27  10U-10-X6S-S6-MU  [C0603]  479.42 290.83 0 bottom
UNK2CA28  10U-10-X6S-S6-MU  [C0603]  468 290.83 180 bottom
UNK2CA29  10U-10-X6S-S6-MU  [C0603]  479.42 274.32 0 bottom
UNK2CA30  NC/47U-10-X5R-S8-TDK  [C0805]  86.22 249.86 180 bottom
UNK2CA31  10U-10-X6S-S6-MU  [C0603]  86.32 247.96 180 bottom
UNK2CA32  NC/10U-10-X6S-S6-MU  [C0603]  512.44 293.37 0 bottom
UNK2CA33  NC/47U-10-X5R-S8-TDK  [C0805]  512.55 295.27 0 bottom
UNK2CA34  10U-10-X6S-S6-MU  [C0603]  512.44 290.83 0 bottom
UNK2CA35  NC/10U-10-X6S-S6-MU  [C0603]  484.5 276.86 180 bottom
UNK2CA36  NC/47U-10-X5R-S8-TDK  [C0805]  484.4 278.76 180 bottom
UNK2CA37  10U-10-X6S-S6-MU  [C0603]  484.5 274.32 180 bottom
UNK2CA38  NC/10U-10-X6S-S6-MU  [C0603]  468 276.86 180 bottom
UNK2CA39  NC/47U-10-X5R-S8-TDK  [C0805]  467.89 278.76 180 bottom
UNK2CA40  10U-10-X6S-S6-MU  [C0603]  468 274.32 180 bottom
UNK2CC1  0.47U-10-X6S-S2-TY  [C0201]  317.98 224.12 90 bottom
UNK2CC2  4.7U-10-X6T-S4-MU  [C0402]  316.32 222.4 270 bottom
UNK2CC4  0.47U-10-X6S-S2-TY  [C0201]  309.81 247.93 0 bottom
UNK2CC6  0.47U-10-X6S-S2-TY  [C0201]  330.17 224.12 90 bottom
UNK2CC7  0.47U-10-X6S-S2-TY  [C0201]  309.81 246.66 0 bottom
UNK2CC8  0.47U-10-X6S-S2-TY  [C0201]  343.63 224.12 90 bottom
UNK2CC9  0.47U-10-X6S-S2-TY  [C0201]  334.61 266.16 270 bottom
UNK2CC11  0.47U-10-X6S-S2-TY  [C0201]  331.06 224.12 90 bottom
UNK2CC13  0.47U-10-X6S-S2-TY  [C0201]  336.77 224.12 90 bottom
UNK2CC15  4.7U-2.5-X6S-S2-MU  [C0201]  339.65 264.95 90 bottom
UNK2CC16  NC/4.7U-2.5-X6S-S2-MU  [C0201]  351.64 249.5 0 bottom
UNK2CC17  4.7U-2.5-X6S-S2-MU  [C0201]  309.81 253.69 0 bottom
UNK2CC19  0.47U-10-X6S-S2-TY  [C0201]  332.83 266.16 270 bottom
UNK2CC20  4.7U-10-X6T-S4-MU  [C0402]  334.11 267.66 0 bottom
UNK2CC22  0.47U-10-X6S-S2-TY  [C0201]  331.05 266.16 270 bottom
UNK2CC23  4.7U-10-X6T-S4-MU  [C0402]  330.34 253.09 270 bottom
UNK2CC25  0.47U-10-X6S-S2-TY  [C0201]  352.85 245.18 180 bottom
UNK2CC26  0.47U-10-X6S-S2-TY  [C0201]  333.72 266.16 270 bottom
UNK2CC27  0.47U-10-X6S-S2-TY  [C0201]  352.85 249.5 180 bottom
UNK2CC28  0.47U-10-X6S-S2-TY  [C0201]  339.65 266.16 270 bottom
UNK2CC29  0.47U-10-X6S-S2-TY  [C0201]  311.03 253.69 180 bottom
UNK2CC30  0.47U-10-X6S-S2-TY  [C0201]  309.81 243.41 0 bottom
UNK2CC31  0.47U-10-X6S-S2-TY  [C0201]  329.28 224.12 90 bottom
UNK2CC32  0.47U-10-X6S-S2-TY  [C0201]  342.36 224.12 90 bottom
UNK2CC33  0.47U-10-X6S-S2-TY  [C0201]  352.85 243.91 180 bottom
UNK2CC34  0.47U-10-X6S-S2-TY  [C0201]  331.94 266.16 270 bottom
UNK2CC35  0.47U-10-X6S-S2-TY  [C0201]  352.85 241.37 180 bottom
UNK2CC36  0.47U-10-X6S-S2-TY  [C0201]  352.85 242.64 180 bottom
UNK2CC37  0.47U-10-X6S-S2-TY  [C0201]  327.57 264.95 90 bottom
UNK2CC38  NC/4.7U-2.5-X6S-S2-MU  [C0201]  327.57 266.16 270 bottom
UNK2CC39  0.47U-10-X6S-S2-TY  [C0201]  311.03 249.2 180 bottom
UNK2CC40  4.7U-2.5-X6S-S2-MU  [C0201]  338.5 246.67 180 bottom
UNK2CC41  4.7U-2.5-X6S-S2-MU  [C0201]  309.81 249.2 0 bottom
UNK2CC42  4.7U-2.5-X6S-S2-MU  [C0201]  331.54 253.03 90 bottom
UNK2CD1  0.1U-10-X7R-S2-MU  [C0201]  317.98 225.34 270 top
UNK2CD3  0.1U-10-X7R-S2-MU  [C0201]  351.64 241.37 0 top
UNK2CD4  0.1U-10-X7R-S2-MU  [C0201]  334.61 264.95 90 top
UNK2CD5  0.1U-10-X7R-S2-MU  [C0201]  343.63 225.34 270 top
UNK2CD6  0.1U-10-X7R-S2-MU  [C0201]  311.03 246.66 180 top
UNK2CD7  0.1U-10-X7R-S2-MU  [C0201]  351.64 242.64 0 top
UNK2CD8  0.1U-10-X7R-S2-MU  [C0201]  331.06 225.34 270 top
UNK2CD9  0.1U-10-X7R-S2-MU  [C0201]  336.77 225.34 270 top
UNK2CD10  0.1U-10-X7R-S2-MU  [C0201]  351.64 249.5 0 top
UNK2CD11  0.1U-10-X7R-S2-MU  [C0201]  339.65 264.95 90 top
UNK2CD12  0.1U-10-X7R-S2-MU  [C0201]  311.03 253.69 180 top
UNK2CD13  0.1U-10-X7R-S2-MU  [C0201]  332.83 264.95 90 top
UNK2CD14  0.1U-10-X7R-S2-MU  [C0201]  331.05 264.95 90 top
UNK2CD15  0.1U-10-X7R-S2-MU  [C0201]  351.64 245.18 0 top
UNK2CD16  0.1U-10-X7R-S2-MU  [C0201]  333.72 264.95 90 top
UNK2CD17  0.1U-10-X7R-S2-MU  [C0201]  311.03 247.93 180 top
UNK2CD18  0.1U-10-X7R-S2-MU  [C0201]  331.94 264.95 90 top
UNK2CD19  0.1U-10-X7R-S2-MU  [C0201]  311.03 243.41 180 top
UNK2CD20  0.1U-10-X7R-S2-MU  [C0201]  351.64 243.91 0 top
UNK2CD21  0.1U-10-X7R-S2-MU  [C0201]  342.36 225.34 270 top
UNK2CD22  0.1U-10-X7R-S2-MU  [C0201]  329.28 225.34 270 top
UNK2CD23  0.1U-10-X7R-S2-MU  [C0201]  330.17 225.34 270 top
UNK2CD24  0.1U-10-X7R-S2-MU  [C0201]  327.57 264.95 90 top
UNK2CD25  0.1U-10-X7R-S2-MU  [C0201]  311.03 249.2 180 top
UNK2GND1  TP01  [TP_040_T]  450.43 295.27 0 top
UNK2GND2  TP01  [TP_040_T]  463.97 295.27 180 top
UNK2GND3  TP01  [TP_040_T]  483.45 295.27 0 top
UNK2GND4  TP01  [TP_040_T]  450.43 278.76 0 top
UNK2GND5  TP01  [TP_040_T]  463.97 278.76 180 top
UNK2GND6  TP01  [TP_040_T]  483.45 278.76 0 top
UNK2GND7  TP01  [TP_040_T]  480.48 295.27 180 top
UNK2GND8  TP01  [TP_040_T]  466.94 295.27 0 top
UNK2GND9  TP01  [TP_040_T]  480.48 278.76 180 top
UNK2GND10  TP01  [TP_040_T]  90.11 249.76 0 top
UNK2GND11  TP01  [TP_040_T]  85.24 249.81 0 top
UNK2GND12  TP01  [TP_040_T]  513.5 295.27 180 top
UNK2GND13  TP01  [TP_040_T]  496.99 278.76 180 top
UNK2GND14  TP01  [TP_040_T]  466.94 278.76 0 top
UNK2J1  HDR-2X1-M  [JP_2P_100]  468.63 233.43 90 bottom
UNK2J2  HDR-3X1-M  [JP_3P_100]  490.87 228.66 270 bottom
UNK2J3  HDR-3X1-M  [JP_3P_100]  490.87 214.94 270 bottom
UNK2J4  HDR-2X1-M  [JP_2P_100]  483.11 243.33 270 bottom
UNK2J5  HDR-2X1-M  [JP_2P_100]  483.11 231.65 270 bottom
UNK2K1  G6K-2F-RF-T-5V-SPECIAL  [RL_G6K2FRT_8P_5V_GR]  414.27 293.12 0 bottom
UNK2K2  G6K-2F-RF-T-5V-SPECIAL  [RL_G6K2FRT_8P_5V_GR]  414.27 277.37 0 bottom
UNK2K3  G6K-2F-RF-T-5V-SPECIAL  [RL_G6K2FRT_8P_5V_GR]  400.3 245.11 0 bottom
UNK2K4  G6K-2F-RF-T-5V-SPECIAL  [RL_G6K2FRT_8P_5V_GR]  373.38 277.11 0 bottom
UNK2K5  G6K-2F-RF-T-5V-SPECIAL  [RL_G6K2FRT_8P_5V_GR]  400.3 261.37 0 bottom
UNK2K6  G6K-2F-RF-T-5V-SPECIAL  [RL_G6K2FRT_8P_5V_GR]  400.3 277.11 0 bottom
UNK2K7  G6K-2F-RF-T-5V-SPECIAL  [RL_G6K2FRT_8P_5V_GR]  386.84 277.11 0 bottom
UNK2K8  G6K-2F-RF-T-5V-SPECIAL  [RL_G6K2FRT_8P_5V_GR]  386.84 293.12 0 bottom
UNK2K9  UA2-5NJ-A-V3  [RL_NECUA2_5V_V3]  299.96 235.46 90 bottom
UNK2K10  UA2-5NJ-A-V3  [RL_NECUA2_5V_V3]  467.11 228.6 180 bottom
UNK2K11  G6K-2F-RF-T-5V-SPECIAL  [RL_G6K2FRT_8P_5V_GR]  414.02 261.37 0 bottom
UNK2K12  UA2-5NJ-A-V3  [RL_NECUA2_5V_V3]  299.96 246.89 90 bottom
UNK2K13  UA2-5NJ-A-V3  [RL_NECUA2_5V_V3]  455.68 228.6 0 bottom
UNK2K14  UA2-5NJ-A-V3  [RL_NECUA2_5V_V3]  467.61 213.36 0 bottom
UNK2K15  UA2-5NJ-A-V3  [RL_NECUA2_5V_V3]  455.64 220.9 0 bottom
UNK2K16  G6K-2F-RF-T-5V-SPECIAL  [RL_G6K2FRT_8P_5V_GR]  373.13 261.11 0 bottom
UNK2K17  G6K-2F-RF-T-5V-SPECIAL  [RL_G6K2FRT_8P_5V_GR]  373.38 293.12 0 bottom
UNK2K18  UB2-5NU-B  [RL_NECUB2_5V]  308.45 274.32 0 bottom
UNK2K19  UA2-5NJ-A-V3  [RL_NECUA2_5V_V3]  467.61 220.98 0 bottom
UNK2K20  UA2-5NJ-A-V3  [RL_NECUA2_5V_V3]  455.68 213.36 0 bottom
UNK2K21  G6K-2F-RF-T-5V-SPECIAL  [RL_G6K2FRT_8P_5V_GR]  400.3 293.12 0 bottom
UNK2K22  G6K-2F-RF-T-5V-SPECIAL  [RL_G6K2FRT_8P_5V_GR]  373.13 228.6 0 bottom
UNK2K23  G6K-2F-RF-T-5V-SPECIAL  [RL_G6K2FRT_8P_5V_GR]  386.84 228.85 0 bottom
UNK2K24  G6K-2F-RF-T-5V-SPECIAL  [RL_G6K2FRT_8P_5V_GR]  386.84 245.11 0 bottom
UNK2K25  G6K-2F-RF-T-5V-SPECIAL  [RL_G6K2FRT_8P_5V_GR]  400.3 229.11 0 bottom
UNK2K26  G6K-2F-RF-T-5V-SPECIAL  [RL_G6K2FRT_8P_5V_GR]  393.45 213.36 0 bottom
UNK2K27  G6K-2F-RF-T-5V-SPECIAL  [RL_G6K2FRT_8P_5V_GR]  379.98 213.11 0 bottom
UNK2K28  UA2-5NJ-A-V3  [RL_NECUA2_5V_V3]  479.04 237.49 180 bottom
UNK2K29  G6K-2F-RF-T-5V-SPECIAL  [RL_G6K2FRT_8P_5V_GR]  373.13 245.11 0 bottom
UNK2K30  G6K-2F-RF-T-5V-SPECIAL  [RL_G6K2FRT_8P_5V_GR]  414.27 245.11 0 bottom
UNK2K31  EC2-5NJ-A  [RL_NECEC2_10P_5V]  506.73 294.64 90 bottom
UNK2K33  NC/UA2-5NJ-A-V3  [RL_NECUA2_5V_V3]  455.68 237.74 0 bottom
UNK2K34  EC2-5NJ-A  [RL_NECEC2_10P_5V]  457.2 294.64 90 bottom
UNK2K36  EC2-5NJ-A  [RL_NECEC2_10P_5V]  490.22 294.64 90 bottom
UNK2K37  EC2-5NJ-A  [RL_NECEC2_10P_5V]  457.2 278.13 90 bottom
UNK2K39  EC2-5NJ-A  [RL_NECEC2_10P_5V]  490.22 278.13 90 bottom
UNK2K40  EC2-5NJ-A  [RL_NECEC2_10P_5V]  473.71 294.64 90 bottom
UNK2K42  EC2-5NJ-A  [RL_NECEC2_10P_5V]  473.71 278.13 90 bottom
UNK2K43  G6K-2F-RF-T-5V-SPECIAL  [RL_G6K2FRT_8P_5V_GR]  386.84 261.11 0 bottom
UNK2R1  NC/1M-1-S4  [R0402]  301.23 227.84 180 bottom
UNK2R2  NC/1M-1-S4  [R0402]  298.95 227.84 0 bottom
UNK2R3  NC/100K-1-S4  [R0402]  289.81 130.81 180 bottom
UNK2R4  NC/100K-1-S4  [R0402]  287.27 130.81 180 bottom
UNK2R5  0-5-S4  [R0402]  302.38 272.16 270 bottom
UNK2R6  1M-1-S4  [R0402]  302.38 274.32 270 bottom
UNK2R7  49.9-1-S4  [R0402]  415.95 299.91 180 bottom
UNK2R8  49.9-1-S4  [R0402]  418.1 299.91 180 bottom
UNK2R9  49.9-1-S4  [R0402]  415.95 286.32 180 bottom
UNK2R10  49.9-1-S4  [R0402]  418.1 286.32 180 bottom
UNK2R11  49.9-1-S4  [R0402]  415.95 284.16 180 bottom
UNK2R12  49.9-1-S4  [R0402]  418.1 284.16 180 bottom
UNK2R13  49.9-1-S4  [R0402]  415.95 270.57 180 bottom
UNK2R14  49.9-1-S4  [R0402]  418.1 270.57 180 bottom
UNK2R15  49.9-1-S4  [R0402]  401.98 251.9 180 bottom
UNK2R16  49.9-1-S4  [R0402]  404.13 251.9 180 bottom
UNK2R17  49.9-1-S4  [R0402]  401.98 238.32 180 bottom
UNK2R18  49.9-1-S4  [R0402]  404.13 238.32 180 bottom
UNK2R19  49.9-1-S4  [R0402]  375.06 283.91 180 bottom
UNK2R20  49.9-1-S4  [R0402]  377.2 283.91 180 bottom
UNK2R21  49.9-1-S4  [R0402]  375.06 270.32 180 bottom
UNK2R22  49.9-1-S4  [R0402]  377.2 270.32 180 bottom
UNK2R23  49.9-1-S4  [R0402]  401.98 268.16 180 bottom
UNK2R24  49.9-1-S4  [R0402]  404.13 268.16 180 bottom
UNK2R25  49.9-1-S4  [R0402]  401.98 254.57 180 bottom
UNK2R26  49.9-1-S4  [R0402]  404.13 254.57 180 bottom
UNK2R27  49.9-1-S4  [R0402]  401.98 283.91 180 bottom
UNK2R28  49.9-1-S4  [R0402]  404.13 283.91 180 bottom
UNK2R29  49.9-1-S4  [R0402]  401.98 270.32 180 bottom
UNK2R30  49.9-1-S4  [R0402]  404.13 270.32 180 bottom
UNK2R31  49.9-1-S4  [R0402]  388.52 283.91 180 bottom
UNK2R32  49.9-1-S4  [R0402]  390.66 283.91 180 bottom
UNK2R33  49.9-1-S4  [R0402]  388.52 270.32 180 bottom
UNK2R34  49.9-1-S4  [R0402]  390.66 270.32 180 bottom
UNK2R37  49.9-1-S4  [R0402]  388.52 286.32 180 bottom
UNK2R38  49.9-1-S4  [R0402]  390.66 286.32 180 bottom
UNK2R39  49.9-1-S4  [R0402]  415.7 268.16 180 bottom
UNK2R40  49.9-1-S4  [R0402]  417.84 268.16 180 bottom
UNK2R41  49.9-1-S4  [R0402]  415.7 254.57 180 bottom
UNK2R42  49.9-1-S4  [R0402]  417.84 254.57 180 bottom
UNK2R43  49.9-1-S4  [R0402]  374.8 238.32 180 bottom
UNK2R44  49.9-1-S4  [R0402]  376.95 238.32 180 bottom
UNK2R45  49.9-1-S4  [R0402]  374.8 221.81 180 bottom
UNK2R46  49.9-1-S4  [R0402]  376.95 221.81 180 bottom
UNK2R47  49.9-1-S4  [R0402]  388.52 235.65 180 bottom
UNK2R48  49.9-1-S4  [R0402]  390.66 235.65 180 bottom
UNK2R49  49.9-1-S4  [R0402]  388.52 222.06 180 bottom
UNK2R50  49.9-1-S4  [R0402]  390.66 222.06 180 bottom
UNK2R51  49.9-1-S4  [R0402]  388.52 251.9 180 bottom
UNK2R52  49.9-1-S4  [R0402]  390.66 251.9 180 bottom
UNK2R53  49.9-1-S4  [R0402]  388.52 238.32 180 bottom
UNK2R54  49.9-1-S4  [R0402]  390.66 238.32 180 bottom
UNK2R55  49.9-1-S4  [R0402]  401.98 235.9 180 bottom
UNK2R56  49.9-1-S4  [R0402]  404.13 235.9 180 bottom
UNK2R57  49.9-1-S4  [R0402]  401.98 222.31 180 bottom
UNK2R58  49.9-1-S4  [R0402]  404.13 222.31 180 bottom
UNK2R59  49.9-1-S4  [R0402]  395.12 220.15 180 bottom
UNK2R60  49.9-1-S4  [R0402]  397.27 220.15 180 bottom
UNK2R61  49.9-1-S4  [R0402]  395.12 206.57 180 bottom
UNK2R62  49.9-1-S4  [R0402]  397.27 206.57 180 bottom
UNK2R63  49.9-1-S4  [R0402]  415.95 251.9 180 bottom
UNK2R64  49.9-1-S4  [R0402]  418.1 251.9 180 bottom
UNK2R65  49.9-1-S4  [R0402]  381.66 206.31 180 bottom
UNK2R66  49.9-1-S4  [R0402]  383.81 206.31 180 bottom
UNK2R67  49.9-1-S4  [R0402]  374.8 267.91 180 bottom
UNK2R68  49.9-1-S4  [R0402]  376.95 267.91 180 bottom
UNK2R69  49.9-1-S4  [R0402]  374.8 254.32 180 bottom
UNK2R70  49.9-1-S4  [R0402]  376.95 254.32 180 bottom
UNK2R71  49.9-1-S4  [R0402]  375.06 299.91 180 bottom
UNK2R72  49.9-1-S4  [R0402]  377.2 299.91 180 bottom
UNK2R73  49.9-1-S4  [R0402]  375.06 286.32 180 bottom
UNK2R74  49.9-1-S4  [R0402]  377.2 286.32 180 bottom
UNK2R75  49.9-1-S4  [R0402]  401.98 299.91 180 bottom
UNK2R76  49.9-1-S4  [R0402]  404.13 299.91 180 bottom
UNK2R77  49.9-1-S4  [R0402]  401.98 286.32 180 bottom
UNK2R78  49.9-1-S4  [R0402]  404.13 286.32 180 bottom
UNK2R79  49.9-1-S4  [R0402]  374.8 251.9 180 bottom
UNK2R80  49.9-1-S4  [R0402]  376.95 251.9 180 bottom
UNK2R82  4.7K-1-S4-WA  [R0402]  456.75 233.88 0 bottom
UNK2R83  4.7K-1-S4-WA  [R0402]  482.6 241.3 0 bottom
UNK2R84  4.7K-1-S4-WA  [R0402]  482.6 233.68 0 bottom
UNK2R85  100K-1-S4  [R0402]  465.07 235.71 0 bottom
UNK2R86  4.7K-1-S4-WA  [R0402]  486.3 226.62 0 bottom
UNK2R87  4.7K-1-S4-WA  [R0402]  475.49 230.78 0 bottom
UNK2R88  4.7K-1-S4-WA  [R0402]  478.03 230.78 0 bottom
UNK2R89  4.7K-1-S4-WA  [R0402]  490.6 226.67 180 bottom
UNK2R90  4.7K-1-S4-WA  [R0402]  478.03 218.59 0 bottom
UNK2R91  4.7K-1-S4-WA  [R0402]  480.57 218.59 0 bottom
UNK2R92  4.7K-1-S4-WA  [R0402]  483.11 218.59 0 bottom
UNK2R93  4.7K-1-S4-WA  [R0402]  486.3 212.91 0 bottom
UNK2R94  4.7K-1-S4-WA  [R0402]  475.37 217.23 180 bottom
UNK2R95  4.7K-1-S4-WA  [R0402]  477.93 217.17 0 bottom
UNK2R96  4.7K-1-S4-WA  [R0402]  490.36 212.91 180 bottom
UNK2R97  4.7K-1-S4-WA  [R0402]  477.93 204.98 0 bottom
UNK2R98  4.7K-1-S4-WA  [R0402]  480.47 204.98 0 bottom
UNK2R99  4.7K-1-S4-WA  [R0402]  483.01 204.98 0 bottom
UNK2R100  49.9-1-S4  [R0402]  415.95 238.32 180 bottom
UNK2R101  49.9-1-S4  [R0402]  418.1 238.32 180 bottom
UNK2R102  49.9-1-S4  [R0402]  374.8 235.39 180 bottom
UNK2R103  49.9-1-S4  [R0402]  376.95 235.39 180 bottom
UNK2R104  49.9-1-S4  [R0402]  381.66 219.9 180 bottom
UNK2R105  49.9-1-S4  [R0402]  383.81 219.9 180 bottom
UNK2R117  1K-1-S4  [R0402]  452.18 233.88 0 bottom
UNK2R118  NC/0-5-S4  [R0402]  310.41 245.39 180 bottom
UNK2R119  4.7K-1-S4-WA  [R0402]  452.12 224.79 180 bottom
UNK2R120  4.7K-1-S4-WA  [R0402]  452.12 232.41 180 bottom
UNK2R125  0-5-S4  [R0402]  456.44 209.55 0 bottom
UNK2R126  0-5-S4  [R0402]  452.37 209.55 0 bottom
UNK2R127  0-5-S4  [R0402]  456.69 217.17 0 bottom
UNK2R128  0-5-S4  [R0402]  452.12 217.17 0 bottom
UNK2R129  0-5-S4  [R0402]  301.23 229.11 180 bottom
UNK2R130  0-5-S4  [R0402]  298.95 229.11 0 bottom
UNK2R131  50-0.1-S4-HF-VI  [R0402]  303.77 243.33 90 bottom
UNK2R132  50-0.1-S4-HF-VI  [R0402]  296.15 243.33 90 bottom
UNK2R133  0-5-S4  [R0402]  302.38 276.48 90 bottom
UNK2SH1  SHORT  [DEFAULT_SHORT_SMALL]  462.05 291.99 0 top
UNK2SH2  SHORT  [DEFAULT_SHORT_SMALL]  464 291.99 0 top
UNK2SH3  SHORT  [DEFAULT_SHORT_SMALL]  452.21 291.99 0 top
UNK2SH4  SHORT  [DEFAULT_SHORT_SMALL]  450.26 292.12 180 top
UNK2SH5  SHORT  [DEFAULT_SHORT_SMALL]  485.23 291.99 0 top
UNK2SH6  SHORT  [DEFAULT_SHORT_SMALL]  483.28 292.12 180 top
UNK2SH7  SHORT  [DEFAULT_SHORT_SMALL]  462.05 275.48 0 top
UNK2SH8  SHORT  [DEFAULT_SHORT_SMALL]  450.26 275.61 180 top
UNK2SH9  SHORT  [DEFAULT_SHORT_SMALL]  464 275.48 0 top
UNK2SH10  SHORT  [DEFAULT_SHORT_SMALL]  452.21 275.48 0 top
UNK2SH11  SHORT  [DEFAULT_SHORT_SMALL]  483.28 275.61 180 top
UNK2SH12  SHORT  [DEFAULT_SHORT_SMALL]  495.07 275.48 0 top
UNK2SH13  SHORT  [DEFAULT_SHORT_SMALL]  480.51 291.99 0 top
UNK2SH14  SHORT  [DEFAULT_SHORT_SMALL]  478.56 291.99 0 top
UNK2SH15  SHORT  [DEFAULT_SHORT_SMALL]  466.77 292.12 180 top
UNK2SH16  SHORT  [DEFAULT_SHORT_SMALL]  468.72 291.99 0 top
UNK2SH17  SHORT  [DEFAULT_SHORT_SMALL]  466.77 275.61 180 top
UNK2SH18  SHORT  [DEFAULT_SHORT_SMALL]  478.56 275.48 0 top
UNK2SH19  SHORT  [DEFAULT_SHORT_SMALL]  90.17 246.75 0 top
UNK2SH20  SHORT  [DEFAULT_SHORT_SMALL]  92.37 246.75 0 top
UNK2SH21  SHORT  [DEFAULT_SHORT_SMALL]  85.31 246.8 0 top
UNK2SH22  SHORT  [DEFAULT_SHORT_SMALL]  87.51 246.8 0 top
UNK2SH23  SHORT  [DEFAULT_SHORT_SMALL]  511.58 291.99 0 top
UNK2SH24  SHORT  [DEFAULT_SHORT_SMALL]  513.76 291.86 180 top
UNK2SH25  SHORT  [DEFAULT_SHORT_SMALL]  485.23 275.48 0 top
UNK2SH26  SHORT  [DEFAULT_SHORT_SMALL]  497.02 275.48 0 top
UNK2SH27  SHORT  [DEFAULT_SHORT_SMALL]  468.72 275.48 0 top
UNK2SH28  SHORT  [DEFAULT_SHORT_SMALL]  480.51 275.48 0 top
UNK2TP_AUXVCC  TP01  [TP_040_T]  92.04 247.9 180 top
UNK2TP_AVDD11_RX  TP01  [TP_040_T]  452.33 276.86 180 top
UNK2TP_AVDD11_XTAL  TP01  [TP_040_T]  511.6 293.37 0 top
UNK2TP_AVDD18_RX  TP01  [TP_040_T]  462.07 276.86 0 top
UNK2TP_PLL_M_VDD33  TP01  [TP_040_T]  478.58 293.37 0 top
UNK2TP_PLL_TX_VDD33  TP01  [TP_040_T]  468.84 293.37 180 top
UNK2TP_VCC3V3  TP01  [TP_040_T]  87.17 247.96 180 top
UNK2TP_VDD_IO_33  TP01  [TP_040_T]  452.33 293.37 180 top
UNK2TP_VDD_TXREG_33_B  TP01  [TP_040_T]  478.58 276.86 0 top
UNK2TP_VDD_TXREG_33_T  TP01  [TP_040_T]  468.84 276.86 180 top
UNK2TP_VDDA_33_LV  TP01  [TP_040_T]  462.07 293.37 0 top
UNK2TP_VDDC_11  TP01  [TP_040_T]  485.35 293.37 180 top
UNK2TP_VDDTXPST_11_B  TP01  [TP_040_T]  495.09 276.86 0 top
UNK2TP_VDDTXPST_11_T  TP01  [TP_040_T]  485.35 276.86 180 top
UNK2TP_XTAL_IN  TP01  [TP_040_T]  306.85 271.67 0 top
UNK2TP_XTAL_OUT  TP01  [TP_040_T]  306.85 276.97 0 top
UNK2U1  SOLDER-DIP8-SOCKET  [DIP8_300X100_RLPIN]  474.97 228.55 270 bottom
UNK2U2  SOLDER-DIP8-SOCKET  [DIP8_300X100_RLPIN]  474.87 214.94 270 bottom
UNK2UF1  MX25L4006EM2I-12G-SOP8  [SOCKET_CODE]  360.09 283.74 180 top
UNK2UF2  MX25L4006EM2I-12G-SOP8  [SOCKET_CODE]  474.97 228.55 90 top
UNK2Y1  XTAL27M-S2520-ABRACON-10P  [XTAL_2X2P5MM_4P]  298.76 274.89 270 bottom
UNK2Y2  NC/XTAL27M-S3225-TXC-10P  [XTAL_3P2X2P5MM_4P_TXC_0201]  298.76 274.89 270 bottom
UNK3C3  0.1U-16-X-S4-MU  [C0402]  192.28 132.33 180 bottom
UNK3C4  0.1U-16-X-S4-MU  [C0402]  189.74 132.33 180 bottom
UNK3C5  22P-50-N-S4-AVX  [C0402]  221.21 217.48 90 bottom
UNK3C6  22P-50-N-S4-AVX  [C0402]  221.21 211.16 270 bottom
UNK3C7  0.1U-16-X-S4-MU  [C0402]  111 186.44 0 bottom
UNK3C8  0.1U-16-X-S4-MU  [C0402]  104.39 171.81 180 bottom
UNK3C9  0.1U-16-X-S4-MU  [C0402]  104.49 185.42 180 bottom
UNK3CA1  NC/10U-10-X6S-S6-MU  [C0603]  112.39 290.83 0 bottom
UNK3CA2  NC/47U-10-X5R-S8-TDK  [C0805]  112.5 292.74 0 bottom
UNK3CA3  NC/10U-10-X6S-S6-MU  [C0603]  100.96 290.83 180 bottom
UNK3CA4  NC/47U-10-X5R-S8-TDK  [C0805]  100.86 292.74 180 bottom
UNK3CA5  NC/10U-10-X6S-S6-MU  [C0603]  100.96 274.32 180 bottom
UNK3CA6  NC/47U-10-X5R-S8-TDK  [C0805]  100.86 276.23 180 bottom
UNK3CA7  NC/10U-10-X6S-S6-MU  [C0603]  128.9 274.32 0 bottom
UNK3CA8  NC/47U-10-X5R-S8-TDK  [C0805]  129.01 276.23 0 bottom
UNK3CA9  NC/10U-10-X6S-S6-MU  [C0603]  117.47 274.32 180 bottom
UNK3CA10  NC/47U-10-X5R-S8-TDK  [C0805]  117.37 276.23 180 bottom
UNK3CA11  NC/10U-10-X6S-S6-MU  [C0603]  76.83 290.83 0 bottom
UNK3CA12  NC/47U-10-X5R-S8-TDK  [C0805]  76.94 292.74 0 bottom
UNK3CA13  NC/47U-10-X5R-S8-TDK  [C0805]  94.72 292.74 0 bottom
UNK3CA14  NC/10U-10-X6S-S6-MU  [C0603]  94.61 290.83 0 bottom
UNK3CA15  NC/47U-10-X5R-S8-TDK  [C0805]  83.08 292.74 180 bottom
UNK3CA16  NC/10U-10-X6S-S6-MU  [C0603]  83.18 290.83 180 bottom
UNK3CA17  NC/47U-10-X5R-S8-TDK  [C0805]  76.94 276.23 0 bottom
UNK3CA18  NC/10U-10-X6S-S6-MU  [C0603]  76.83 274.32 0 bottom
UNK3CA19  NC/47U-10-X5R-S8-TDK  [C0805]  111.1 249.13 180 bottom
UNK3CA20  NC/10U-10-X6S-S6-MU  [C0603]  111.2 247.23 180 bottom
UNK3CA21  10U-10-X6S-S6-MU  [C0603]  112.39 288.29 0 bottom
UNK3CA22  10U-10-X6S-S6-MU  [C0603]  100.96 288.29 180 bottom
UNK3CA23  10U-10-X6S-S6-MU  [C0603]  100.96 271.78 180 bottom
